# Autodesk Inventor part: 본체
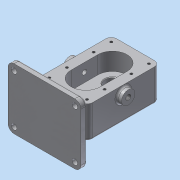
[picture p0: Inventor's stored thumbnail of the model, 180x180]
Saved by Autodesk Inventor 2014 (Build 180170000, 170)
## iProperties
Created: 2026-10
Part Number: 본체
Material: 알루미늄 6061
Document SubType Name: Modeling
Designer: dg
Density: 2.71 g/cm^3
Appearance: 알루미늄 - 평지
Mass: 1478.81 g
Surface Area: 817.868 cm^2
Volume: 545.687 cm^3
Author: dg
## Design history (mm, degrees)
sketch "스케치1"
  geometry: L1 (-40, 60)-(40, 60); L2 (40, 60)-(40, -60); L3 (40, -60)-(-40, -60); L4 (-40, -60)-(-40, 60); L5 (0, 22)-(0, -22); L6 (-24, 22)-(-24, -22); L7 (24, -22)-(24, 22); A1 r 24 centre (0, 22) between (24, 22) and (-24, 22); A2 r 24 centre (0, -22) between (-24, -22) and (24, -22); 4 further points
  constraints: 16 end point, 4 parallel, 4 point on circle, 4 tangent, 3 midpoint, 2 centre point, 1 coincident, 1 horizontal, 1 horizontal alignment, 1 perpendicular, 1 vertical alignment
  dimensions: "d0" = 80 distance of L1.start L1.end; "d1" = 120 distance of L1.end L2.end; "d2" = 44 distance of L5.start L5.end; "d3" = 48 diameter of A1
extrude "돌출1" new body sketch "스케치1" distance "d4" = 53; taper "d5" = 0 deg
extrude "돌출2" cut sketch "스케치1" distance "d6" = 29; taper "d7" = 0 deg
fillet "모깎기1" dims "d8" = 9
sketch "스케치2"
  geometry: L1 (-80, 30)-(-90, 30); L2 (-90, 30)-(-90, -70); L3 (-90, -70)-(-80, -70); L4 (-80, -70)-(-80, 30); L5 (22, -29)-(22, -70); L6 (60, 0)-(-60, 0) reference; L7 (22, -29)-(46, -29) reference; L8 (-22, -29)-(22, -29) reference; L9 (22, -29)-(41, -29); L10 (34.5, -29)-(34.5, -44); L11 (34.5, -44)-(30.5, -44); L12 (30.5, -44)-(30.5, -62.7); L13 (22, -70)-(41, -70); L14 (41, -70)-(41, -29); L15 (30.5, -62.7)-(36, -62.7); L16 (36, -62.7)-(36, -70); L17 (-60, -53)-(-60, 0) reference; L18 (-60, -11.547)-(-80, 0); L19 (-60, -41.453)-(-80, -53); L20 (-22, -29)-(-22, -53); L21 (-51, -53)-(51, -53) reference; L22 (-22, -29)-(-9.5, -29); L23 (-9.5, -29)-(-9.5, -44); L24 (-9.5, -44)-(-22, -44); 1 further point
  constraints: 38 end point, 13 point on line, 9 perpendicular, 5 parallel, 2 horizontal alignment, 1 equal length, 1 horizontal
  dimensions: "d9" = 22 distance from line of point (0, 0) L5; "d10" = 25 diameter of L10 L5; "d11" = 38 diameter of L14 L5; "d12" = 15 distance of L10.start L10.end; "d13" = 17 diameter of L12 L5; "d14" = 28 diameter of L16 L5; "d15" = 7.3 distance of L15.end L16.end; "d16" = 70 distance between parallel lines of L13 L6; "d17" = 10 distance of L1.start L1.end; "d18" = 100 distance of L1.end L2.end; "d19" = 90 distance from line of point (0, 0) L2; "d20" = 53 distance of L19.end L18.end; "d21" = 60 deg angle of L4 L18; "d22" = 17 distance from line of L3 L19.end; "d23" = 44 distance from line of L20 L5.start; "d24" = 25 diameter of L23 L20
revolve "회전1" stored, may be unused: angle "d25" = 90 deg
extrude "돌출3" join sketch "스케치2" stored distance "d26" = 120; taper "d27" = 0 deg
extrude "돌출4" join sketch "스케치2" stored distance "d28" = 48; taper "d29" = 0 deg
revolve "회전2" stored, may be unused: angle "d30" = 90 deg
revolve "회전3" stored, may be unused: angle "d31" = 90 deg
fillet "모깎기2" dims "d32" = 10
hole "구멍1" diameter "d35" = 9; stored, may be unused: countersink angle "d39" = 90 deg, drill point angle "d41" = 118 deg; dims "d33" = 10, "d34" = 10, "d36" = 6, "d37" = 4, "d38" = 2, "d40" = 8
node "작업 평면1"
fillet "모깎기3" dims "d42" = 0.5
chamfer "모따기1" distance "d43" = 0.7; stored, may be unused: second distance "d44" = 2, angle "d45" = 30 deg
node "작업 평면2"
sketch "스케치3"
  geometry: C1 r 11 at (0, -14); 1 further point
  constraints: 1 centre point, 1 vertical alignment
  dimensions: "d47" = 14 distance of point (0, 0) C1.centre; "d48" = 22 diameter of C1
extrude "돌출5" join sketch "스케치3" stored distance "d49" = 48; taper "d50" = 0 deg
hole "구멍2" diameter "d53" = 7.647; stored, may be unused: countersink angle "d59" = 90 deg, drill point angle "d61" = 118 deg; dims "d51" = 10, "d52" = 10, "d54" = 9, "d55" = 0.62479, "d56" = 7.985, "d57" = 4, "d58" = 2, "d60" = 8
fillet "모깎기4" dims "d62" = 3
fillet "모깎기5" dims "d63" = 3
fillet "모깎기6" dims "d64" = 3
fillet "모깎기7" dims "d65" = 3
sketch "스케치4" dims "d0" = 80, "d1" = 120, "d2" = 44, "d3" = 48
  geometry: L1 (100, 0)-(0, 0) reference; L2 (0, 100)-(100, 100) reference; 3 further points
  constraints: 1 midpoint, 1 vertical alignment, 1 other
  dimensions: "d66" = 10 distance from line of L1 point (50, 10)
feature "엠보싱1" sketch "스케치4" dims "d0" = 80, "d1" = 120, "d2" = 44, "d3" = 48, "d67" = 0.5, "d68" = 0
fillet "모깎기8" dims "d69" = 3
sketch "스케치5"
  geometry: A1 r 9 centre (31, 51) between (40, 51) and (31, 60) reference; A2 r 9 centre (-31, 51) between (-31, 60) and (-40, 51) reference; 5 further points
  constraints: 2 coincident, 2 vertical alignment, 1 horizontal alignment
  dimensions: "d70" = 29 distance of point (-31, 22) point (-31, 51)
hole "구멍3" sketch "스케치5" at (-31, 51), (31, 51), (31, 22), (-31, 22) diameter "d71" = 4.134; stored, may be unused: countersink angle "d75" = 82 deg, drill point angle "d77" = 118 deg; dims "d72" = 10, "d73" = 3.023, "d74" = 2, "d76" = 12
chamfer "모따기2" distance "d78" = 1; stored, may be unused: second distance "d79" = 2, angle "d80" = 30 deg
node "솔리드1"
mirror "대칭1"
mirror "대칭2"
mirror "대칭3"
mirror "대칭4"
other parameters: "d46" = 48
